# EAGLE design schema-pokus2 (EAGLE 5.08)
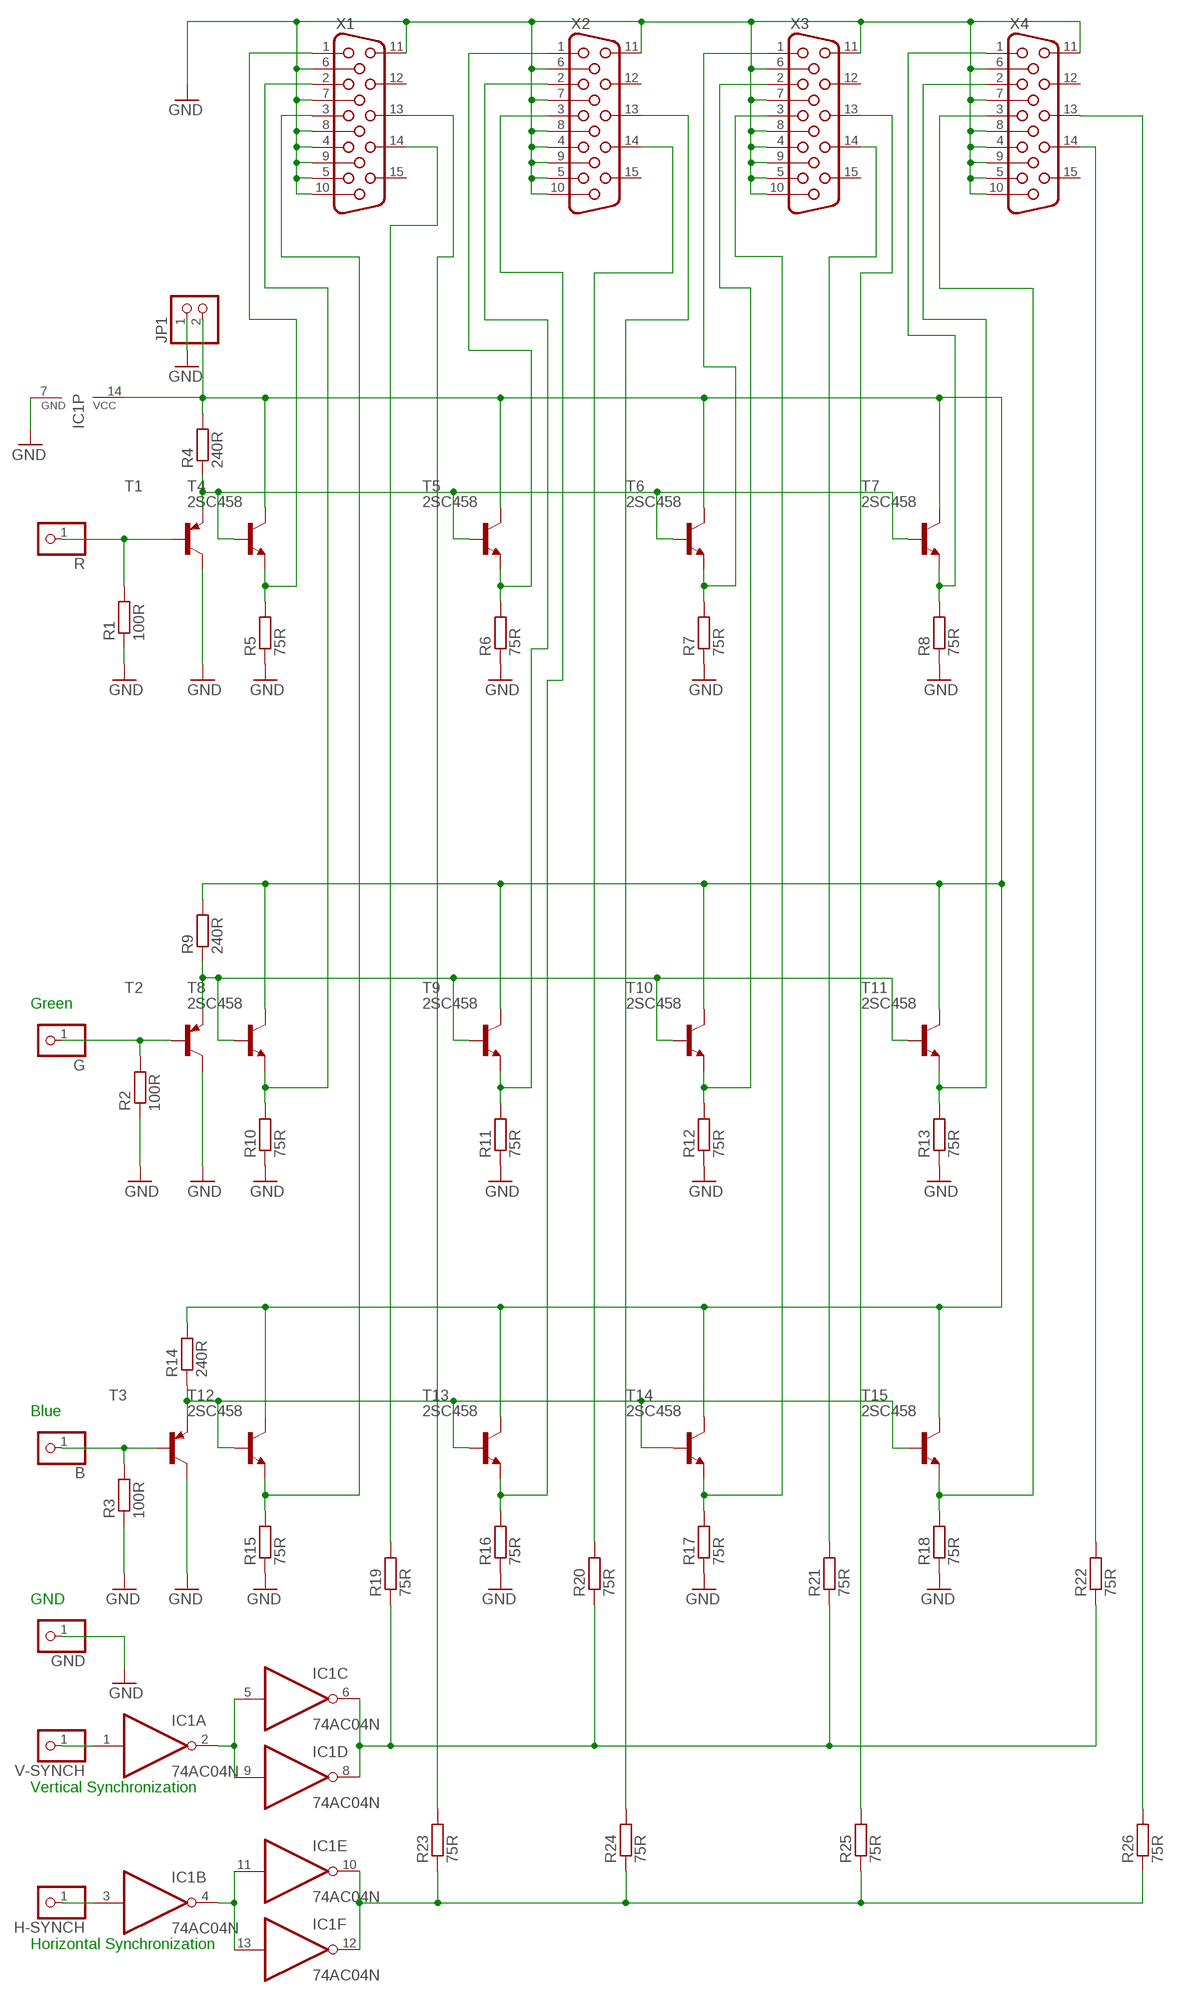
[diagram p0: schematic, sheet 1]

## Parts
B  PINHD-1X1  [1X01]
G  PINHD-1X1  [1X01]
GND  PINHD-1X1  [1X01]
H-SYNCH  PINHD-1X1  [1X01]
IC1  74AC04N  [DIL14]
JP1  PINHD-1X2  [1X02]
R  PINHD-1X1  [1X01]
R1  100R  R-EU_0207/10  [0207/10]
R2  100R  R-EU_0207/10  [0207/10]
R3  100R  R-EU_0207/10  [0207/10]
R4  240R  R-EU_0204/7  [0204/7]
R5  75R  R-EU_0207/12  [0207/12]
R6  75R  R-EU_0207/12  [0207/12]
R7  75R  R-EU_0207/12  [0207/12]
R8  75R  R-EU_0207/12  [0207/12]
R9  240R  R-EU_0204/7  [0204/7]
R10  75R  R-EU_0207/12  [0207/12]
R11  75R  R-EU_0207/12  [0207/12]
R12  75R  R-EU_0207/12  [0207/12]
R13  75R  R-EU_0207/12  [0207/12]
R14  240R  R-EU_0204/7  [0204/7]
R15  75R  R-EU_0207/12  [0207/12]
R16  75R  R-EU_0207/12  [0207/12]
R17  75R  R-EU_0207/12  [0207/12]
R18  75R  R-EU_0207/12  [0207/12]
R19  75R  R-EU_0207/7  [0207/7]
R20  75R  R-EU_0207/7  [0207/7]
R21  75R  R-EU_0207/7  [0207/7]
R22  75R  R-EU_0207/7  [0207/7]
R23  75R  R-EU_0204/7  [0204/7]
R24  75R  R-EU_0204/7  [0204/7]
R25  75R  R-EU_0204/7  [0204/7]
R26  75R  R-EU_0204/7  [0204/7]
T1  -PNP-TO92-BEC  [TO92-BEC]
T2  -PNP-TO92-BEC  [TO92-BEC]
T3  -PNP-TO92-BEC  [TO92-BEC]
T4  2SC458  [TO92-ECB]
T5  2SC458  [TO92-ECB]
T6  2SC458  [TO92-ECB]
T7  2SC458  [TO92-ECB]
T8  2SC458  [TO92-ECB]
T9  2SC458  [TO92-ECB]
T10  2SC458  [TO92-ECB]
T11  2SC458  [TO92-ECB]
T12  2SC458  [TO92-ECB]
T13  2SC458  [TO92-ECB]
T14  2SC458  [TO92-ECB]
T15  2SC458  [TO92-ECB]
V-SYNCH  PINHD-1X1  [1X01]
X1  HF15H  [HDF15H]
X2  HF15H  [HDF15H]
X3  HF15H  [HDF15H]
X4  HF15H  [HDF15H]

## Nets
N$1: R9.1 T2.E T8.B T9.B T10.B T11.B
N$2: IC1.1(A:I) V-SYNCH.1
N$3: H-SYNCH.1 IC1.3(B:I)
N$4: IC1.2(A:O) IC1.5(C:I) IC1.9(D:I)
N$5: IC1.4(B:O) IC1.11(E:I) IC1.13(F:I)
N$6: IC1.6(C:O) IC1.8(D:O) R19.1 R20.1 R21.1 R22.1
N$7: IC1.10(E:O) IC1.12(F:O) R23.1 R24.1 R25.1 R26.1
N$8: B.1 R3.2 T3.B
N$9: R14.1 T3.E T12.B T13.B T14.B T15.B
N$11: R15.2 T12.E X1.3
N$12: R19.2 X1.14
N$13: R23.2 X1.13
N$14: R16.2 T13.E X2.3
N$15: R20.2 X2.14
N$16: R24.2 X2.13
N$17: R17.2 T14.E X3.3
N$18: R25.2 X3.13
N$19: R21.2 X3.14
N$20: GND.1 IC1.7(P:GND) JP1.1 R1.1 R2.1 R3.1 R5.1 R6.1 R7.1 R8.1 R10.1 R11.1 R12.1 R13.1 R15.1 R16.1 R17.1 R18.1 T1.C T2.C T3.C X1.4 X1.5 X1.6 X1.7 X1.8 X1.9 X1.10 X1.11 X2.4 X2.5 X2.6 X2.7 X2.8 X2.9 X2.10 X2.11 X3.4 X3.5 X3.6 X3.7 X3.8 X3.9 X3.10 X3.11 X4.4 X4.5 X4.6 X4.7 X4.8 X4.9 X4.10 X4.11 ; supply symbol labelled GND
N$21: R1.2 R.1 T1.B
N$22: R22.2 X4.14
N$23: R26.2 X4.13
N$24: G.1 R2.2 T2.B
N$25: IC1.14(P:VCC) JP1.2 R4.2 R9.2 R14.2 T4.C T5.C T6.C T7.C T8.C T9.C T10.C T11.C T12.C T13.C T14.C T15.C
N$26: R4.1 T1.E T4.B T5.B T6.B T7.B
N$27: R10.2 T8.E X1.2
N$28: R11.2 T9.E X2.2
N$29: R12.2 T10.E X3.2
N$30: R13.2 T11.E X4.2
N$31: R5.2 T4.E X1.1
N$33: R6.2 T5.E X2.1
N$35: R8.2 T7.E X4.1
N$38: R18.2 T15.E X4.3
N$40: R7.2 T6.E X3.1
Unconnected: X1.12 X1.15 X2.12 X2.15 X3.12 X3.15 X4.12 X4.15

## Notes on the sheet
- Green
- Blue
- GND
- Vertical Synchronization
- Horizontal Synchronization

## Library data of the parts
B G GND H-SYNCH R V-SYNCH = pinhead:PINHD-1X1: PIN HEADER
IC1 = 74xx-eu:74*04: Hex INVERTER
JP1 = pinhead:PINHD-1X2: PIN HEADER
R1-R26 = rcl:R-EU_: RESISTOR, European symbol
T1-T3 = #Upravene tranzistory:*-PNP-: PNP Transistror
T4-T15 = #Upravene tranzistory:2SC458: NPN Silicon Epitaxial Planar Transistor Source: SEMTECH ELECTRONICS LTD. ... 2SC458 1.pdf
X1-X4 = con-subd:HF15: SUB-D

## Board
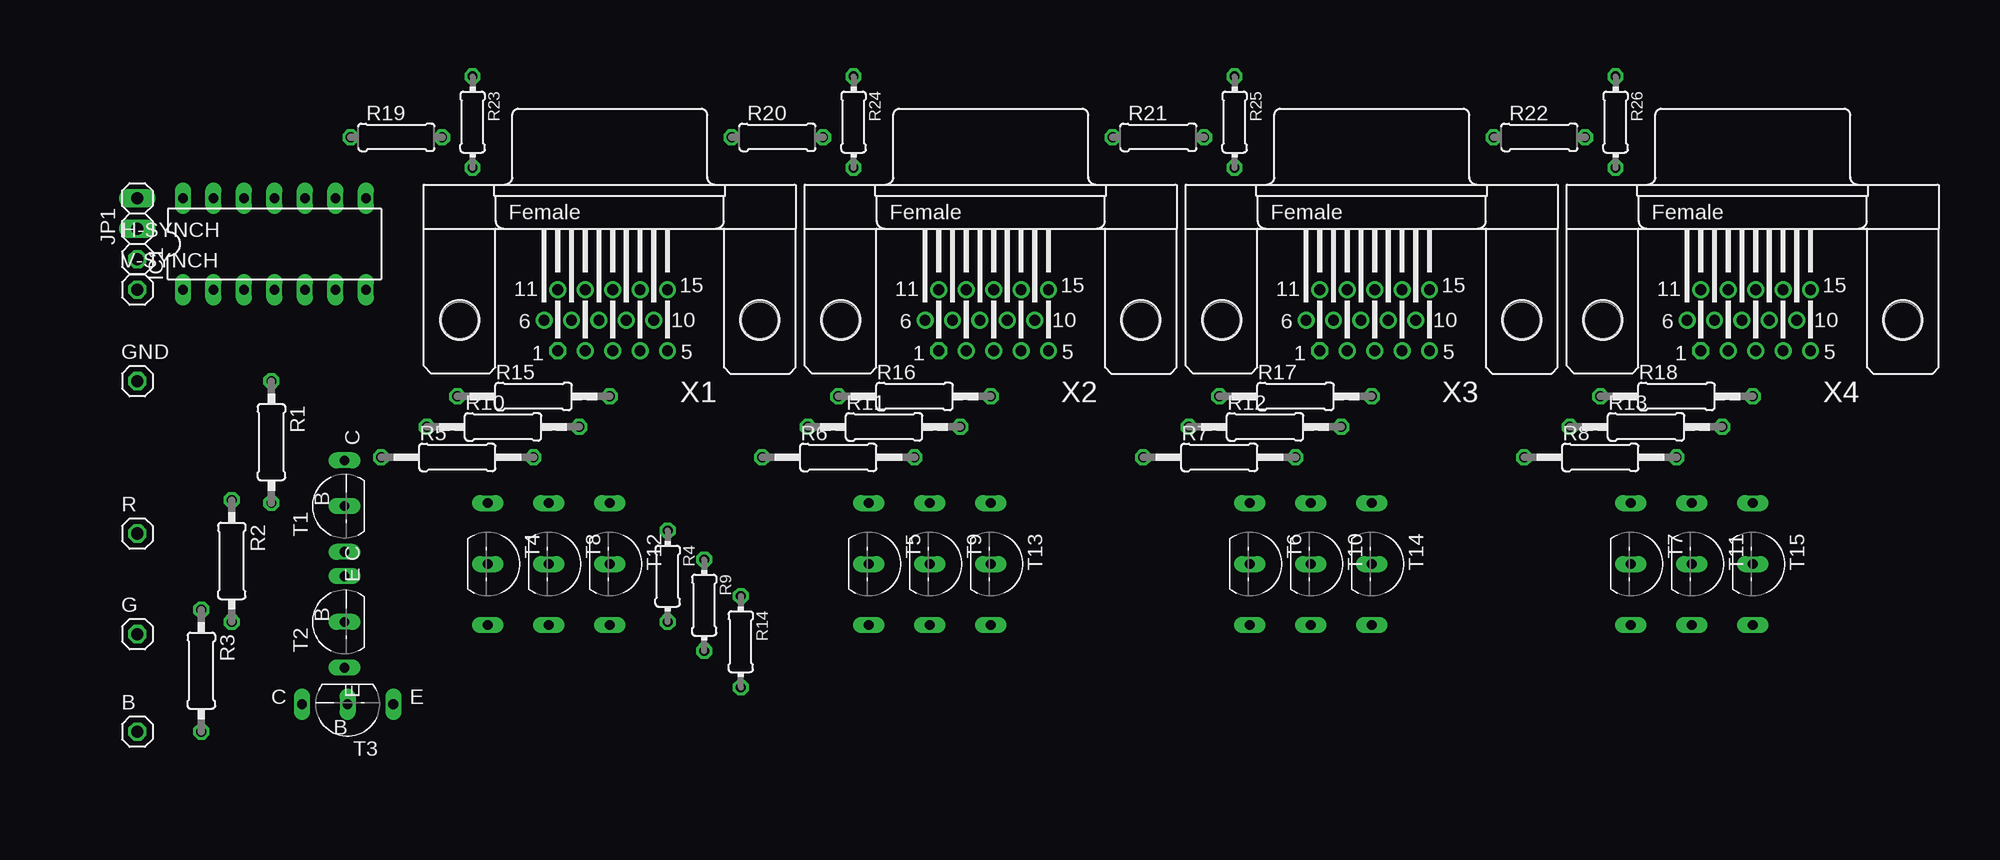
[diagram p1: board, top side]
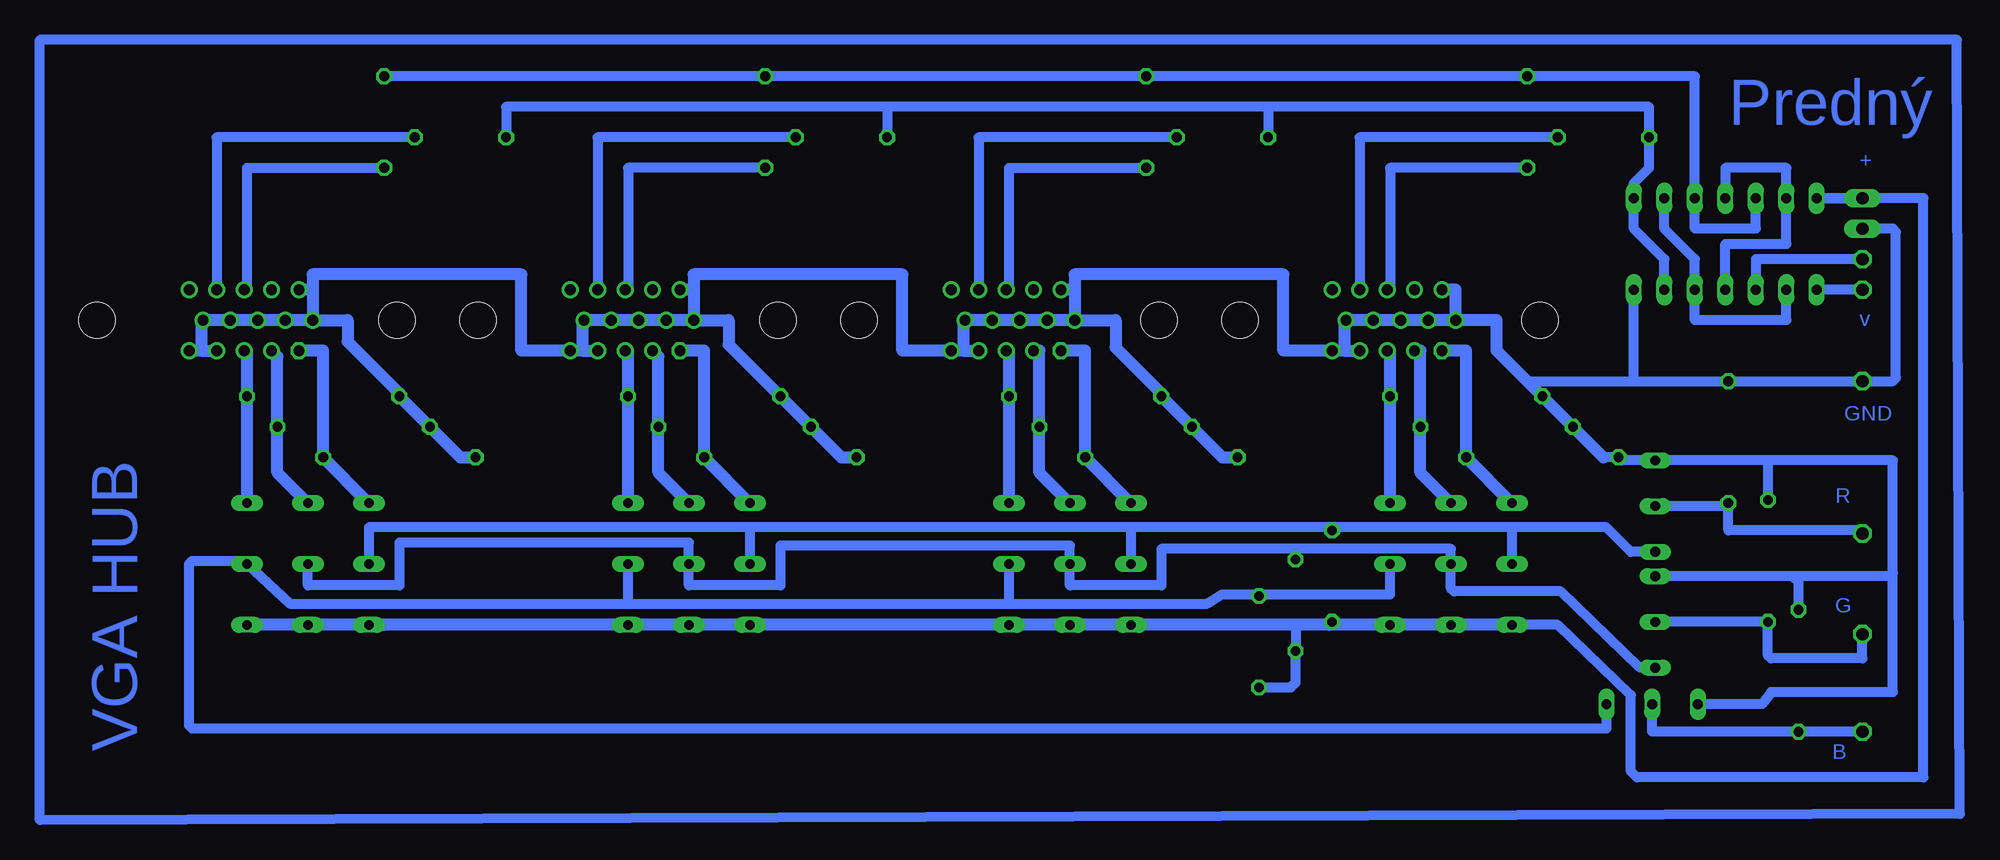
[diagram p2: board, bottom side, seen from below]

No outline drawn. Coordinates in mm, seen from the top.
Copper layers (1*16): Top 0.035mm / dielectric 1.5mm / Bottom 0.035mm
Design rules "default": minimum track width 10mil, minimum drill 24mil, track to track 8mil, track to pad 8mil, pad to pad 8mil, via to via 8mil, smd to smd 8mil, copper to edge 40mil, drill to drill 8mil, minimum pad ring 10mil, minimum via ring 8mil, stop-mask expansion 4mil, vias tented up to drill 0mil, thermal gap 10mil

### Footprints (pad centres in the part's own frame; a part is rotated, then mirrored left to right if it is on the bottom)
1X01 = drill 1.016 octagon: 1 0,0
DIL14 = drill 0.813 long: 1 -7.62,-3.81; 2 -5.08,-3.81; 3 -2.54,-3.81; 4 0,-3.81; 5 2.54,-3.81; 6 5.08,-3.81; 7 7.62,-3.81; 8 7.62,3.81; 9 5.08,3.81; 10 2.54,3.81; 11 0,3.81; 12 -2.54,3.81; 13 -5.08,3.81; 14 -7.62,3.81
1X02 = drill 1.016 long: 1 -1.27,0; 2 1.27,0
0207/10 = drill 0.813 octagon: 1 -5.08,0; 2 5.08,0
0204/7 = drill 0.813 octagon: 1 -3.81,0; 2 3.81,0
0207/12 = drill 0.813 octagon: 1 -6.35,0; 2 6.35,0
0207/7 = drill 0.813 octagon: 1 -3.81,0; 2 3.81,0
TO92-BEC = drill 0.813 long: B 0,0; C 3.81,0; E -3.81,0
TO92-ECB = drill 0.813 long: B 0,0; C 5.08,0; E -5.08,0
HDF15H = drill 0.9 octagon: 1 4.329,2.54 | drill 0.9 round: 2 2.043,2.54; 3 -0.243,2.54; 4 -2.529,2.54; 5 -4.815,2.54; 6 5.472,0; 7 3.186,0; 8 0.9,0; 9 -1.386,0; 10 -3.672,0; 11 4.329,-2.54; 12 2.043,-2.54; 13 -0.243,-2.54; 14 -2.529,-2.54; 15 -4.815,-2.54 | hole 3: -12.5,0; 12.5,0

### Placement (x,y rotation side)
B  -16.51,58.42 0 top
G  -16.51,66.55 0 top
GND  -16.51,87.63 0 top
H-SYNCH  -16.51,97.79 0 top
IC1  -5.08,99.06 0 top
JP1  -16.51,101.6 90 top
R  -16.51,74.93 0 top
R1  -5.33,82.55 270 top
R2  -8.64,72.64 270 top
R3  -11.18,63.5 270 top
R4  27.69,71.37 270 top
R5  10.16,81.28 0 top
R6  41.91,81.28 0 top
R7  73.66,81.28 0 top
R8  105.41,81.28 0 top
R9  30.73,68.96 270 top
R10  13.97,83.82 0 top
R11  45.72,83.82 0 top
R12  77.47,83.82 0 top
R13  109.22,83.82 0 top
R14  33.78,65.91 270 top
R15  16.51,86.36 0 top
R16  48.26,86.36 0 top
R17  80.01,86.36 0 top
R18  111.76,86.36 0 top
R19  5.08,107.95 0 top
R20  36.83,107.95 0 top
R21  68.58,107.95 0 top
R22  100.33,107.95 0 top
R23  11.43,109.22 270 top
R24  43.18,109.22 270 top
R25  74.93,109.22 270 top
R26  106.68,109.22 270 top
T1  0.76,77.22 90 top
T2  0.76,67.56 90 top
T3  1.02,60.71 180 top
T4  12.7,72.39 270 top
T5  44.45,72.39 270 top
T6  76.2,72.39 270 top
T7  107.95,72.39 270 top
T8  17.78,72.39 270 top
T9  49.53,72.39 270 top
T10  81.28,72.39 270 top
T11  113.03,72.39 270 top
T12  22.86,72.39 270 top
T13  54.61,72.39 270 top
T14  86.36,72.39 270 top
T15  118.11,72.39 270 top
V-SYNCH  -16.51,95.25 0 top
X1  22.86,92.71 180 top
X2  54.61,92.71 180 top
X3  86.36,92.71 180 top
X4  118.11,92.71 180 top

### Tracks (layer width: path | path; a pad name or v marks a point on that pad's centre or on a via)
N$1
  Bottom 0.813: 30.48,73.66 17.78,73.66 T8.B 17.78,70.36 17.53,70.1 8.64,70.1 2.03,63.75 T2.E | 30.48,73.66 41.91,73.66 41.91,70.61 49.53,70.61 T9.B 49.53,73.91 73.66,73.91 73.66,70.61 81.28,70.61 T10.B 81.28,74.17 105.41,74.17 105.41,70.61 113.03,70.61 T11.B | R9.1 30.73,73.41 30.48,73.66
N$2
  Bottom 0.813: V-SYNCH.1 IC1.1
N$3
  Bottom 0.813: IC1.3 -7.62,97.79 H-SYNCH.1
N$4
  Bottom 0.813: IC1.9 0,100.33 -2.54,97.79 IC1.5 -2.54,92.71 -10.16,92.71 IC1.2
N$5
  Bottom 0.813: IC1.11 -5.08,105.41 -10.16,105.41 IC1.13 -10.16,99.06 -5.08,99.06 IC1.4
N$6
  Bottom 0.813: 33.02,110.49 1.27,110.49 R19.1 1.27,105.41 2.54,104.14 IC1.8 2.54,100.33 0,97.79 IC1.6 | 33.02,110.49 R20.1 | 33.02,110.49 64.77,110.49 | 64.77,110.49 R21.1 | 64.77,110.49 96.52,110.49 R22.1
N$7
  Bottom 0.813: R26.1 R25.1 R24.1 R23.1 -2.54,113.03 IC1.10 -2.54,100.33 -7.62,100.33 IC1.12
N$8
  Bottom 0.813: B.1 R3.2 1.02,58.42 T3.B
N$9
  Bottom 0.813: T12.B 22.86,69.85 34.29,69.85 | 34.29,69.85 36.83,69.85 38.1,69.09 54.61,69.09 | 54.61,69.09 T13.B | 86.36,69.09 T14.B | 86.36,69.09 54.61,69.09 | 86.36,69.09 114.55,69.09 T15.B 118.36,72.64 122.68,72.64 122.94,72.39 122.94,58.93 122.68,58.67 4.83,58.67 T3.E | R14.1 34.16,69.72 34.29,69.85
N$10
  Bottom 0.813: -24.64,51.56 -24.38,116.08 135.38,116.08 135.38,51.05 -24.64,51.56
N$11
  Bottom 1.016: X1.3 22.86,90.17 R15.2 T12.E
N$12
  Bottom 0.813: X1.14 25.39,107.94 25.4,107.95 R19.2
N$13
  Bottom 0.813: R23.2 22.86,105.41 22.86,95.49 X1.13
N$14
  Bottom 1.016: X2.3 54.61,90.17 R16.2 T13.E
N$15
  Bottom 0.813: R20.2 57.15,107.95 X2.14
N$16
  Bottom 0.813: R24.2 54.61,105.41 54.61,95.49 X2.13
N$17
  Bottom 1.016: X3.3 86.36,89.93 R17.2 T14.E
N$18
  Bottom 0.813: R25.2 86.36,105.41 86.36,95.49 X3.13
N$19
  Bottom 0.813: X3.14 88.89,107.94 88.9,107.95 R21.2
N$20
  Bottom 0.813: 2.54,87.63 IC1.7 | 5.08,81.28 R5.1 3.56,81.03 T1.C -8.64,81.03 | JP1.1 -19.05,100.33 -19.3,100.08 -19.3,87.88 -19.05,87.63 GND.1 R1.1 2.54,87.63 | 2.54,87.63 11.43,87.63 R10.1 | -10.92,71.37 -10.67,71.37 | -10.67,71.37 T2.C | -10.92,71.37 -11.18,71.12 | -8.64,81.03 R2.1 | -8.64,81.03 -19.05,81.03 -19.05,71.63 | -11.18,71.12 R3.1 | -11.18,71.12 -10.92,71.12 -10.67,71.37 | -10.92,71.37 -18.8,71.37 -19.05,71.63 | T3.C -8.13,60.71 -8.89,61.72 -19.05,61.72 -19.05,71.63
  Bottom 1.016: X1.6 X1.7 X1.8 X1.9 X1.10 26.67,92.71 26.67,90.17 | X1.11 17.39,95.25 X1.6 | 26.67,90.17 X1.4 | 26.67,90.17 X1.5 31.75,90.17 31.75,96.52 49.14,96.52 49.14,95.25 | X2.6 X2.7 X2.8 X2.9 X2.10 58.42,92.71 58.42,90.17 | 58.42,90.17 X2.4 | 58.42,90.17 X2.5 63.5,90.17 63.5,96.52 80.89,96.52 80.89,95.25 | 49.14,95.25 X2.11 | 49.14,95.25 X2.6 | X3.6 X3.7 X3.8 X3.9 X3.10 90.17,92.71 90.17,90.17 | 90.17,90.17 X3.4 | 90.17,90.17 X3.5 95.25,90.17 95.25,96.52 112.64,96.52 112.64,95.25 | 80.89,95.25 X3.11 | 80.89,95.25 X3.6 | X4.6 X4.7 X4.8 X4.9 X4.10 121.92,92.71 121.92,90.17 | 121.92,90.17 X4.4 | 121.92,90.17 X4.5 | 112.64,95.25 X4.11 | 112.64,95.25 X4.6 | 5.08,81.28 R10.1 R15.1 11.43,87.63 13.97,90.17 13.97,92.71 X1.6 | R6.1 36.83,81.28 R11.1 R16.1 41.91,86.61 45.72,90.42 45.72,92.71 X2.6 | R7.1 68.58,81.28 R12.1 R17.1 77.98,90.68 77.98,92.71 X3.6 | R8.1 100.33,81.28 R13.1 R18.1 105.41,86.61 109.73,90.93 109.73,92.71 X4.6
N$21
  Bottom 0.813: T1.B -5.08,77.22 R1.2 -5.33,75.18 -16.51,75.18 R.1
N$22
  Bottom 0.813: R22.2 120.65,107.95 X4.14
N$23
  Bottom 0.813: R26.2 118.11,105.41 118.11,95.49 X4.13
N$24
  Bottom 0.813: T2.B R2.2 -8.64,64.77 -8.89,64.52 -16.51,64.52 G.1
N$25
  Bottom 0.813: JP1.2 IC1.14 -21.59,102.87 -21.59,54.61 2.29,54.61 2.79,55.12 2.79,61.47 8.89,67.31 T4.C | 27.94,67.31 R4.2 | 30.48,67.31 30.73,67.06 R9.2 30.73,62.48 31.11,62.1 R14.2
  Bottom 1.016: T15.C T11.C T7.C | T7.C 106.68,67.31 | T7.C T14.C T10.C T6.C T13.C T9.C T5.C 30.48,67.31 27.94,67.31 T12.C T8.C T4.C
N$26
  Bottom 0.813: 12.7,75.44 T4.B | 12.7,75.44 27.94,75.44 | 27.94,75.44 44.45,75.44 | 44.45,75.44 T5.B | 44.45,75.44 76.2,75.44 | 76.2,75.44 T6.B | 76.2,75.44 107.95,75.44 T7.B | 27.94,75.44 R4.1 | T1.E 2.79,73.41 4.83,75.44 12.7,75.44
N$27
  Bottom 1.016: X1.2 20.32,90.17 R10.2 20.32,80.01 T8.E
N$28
  Bottom 1.016: X2.2 52.07,90.17 R11.2 52.07,80.01 T9.E
N$29
  Bottom 1.016: X3.2 83.82,89.67 R12.2 83.82,80.01 T10.E
N$30
  Bottom 1.016: X4.2 115.57,89.67 R13.2 115.57,80.01 T11.E
N$31
  Bottom 1.016: X1.1 16.51,90.17 R5.2 T4.E
N$33
  Bottom 1.016: X2.1 48.26,90.17 R6.2 T5.E
N$35
  Bottom 1.016: T7.E R8.2 111.76,90.17 X4.1
N$38
  Bottom 1.016: X4.3 118.11,89.93 R18.2 T15.E
N$40
  Bottom 1.016: X3.1 80.01,90.17 R7.2 T6.E

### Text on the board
Bottom: Predný | + | v | GND | VGA HUB | R | G | B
